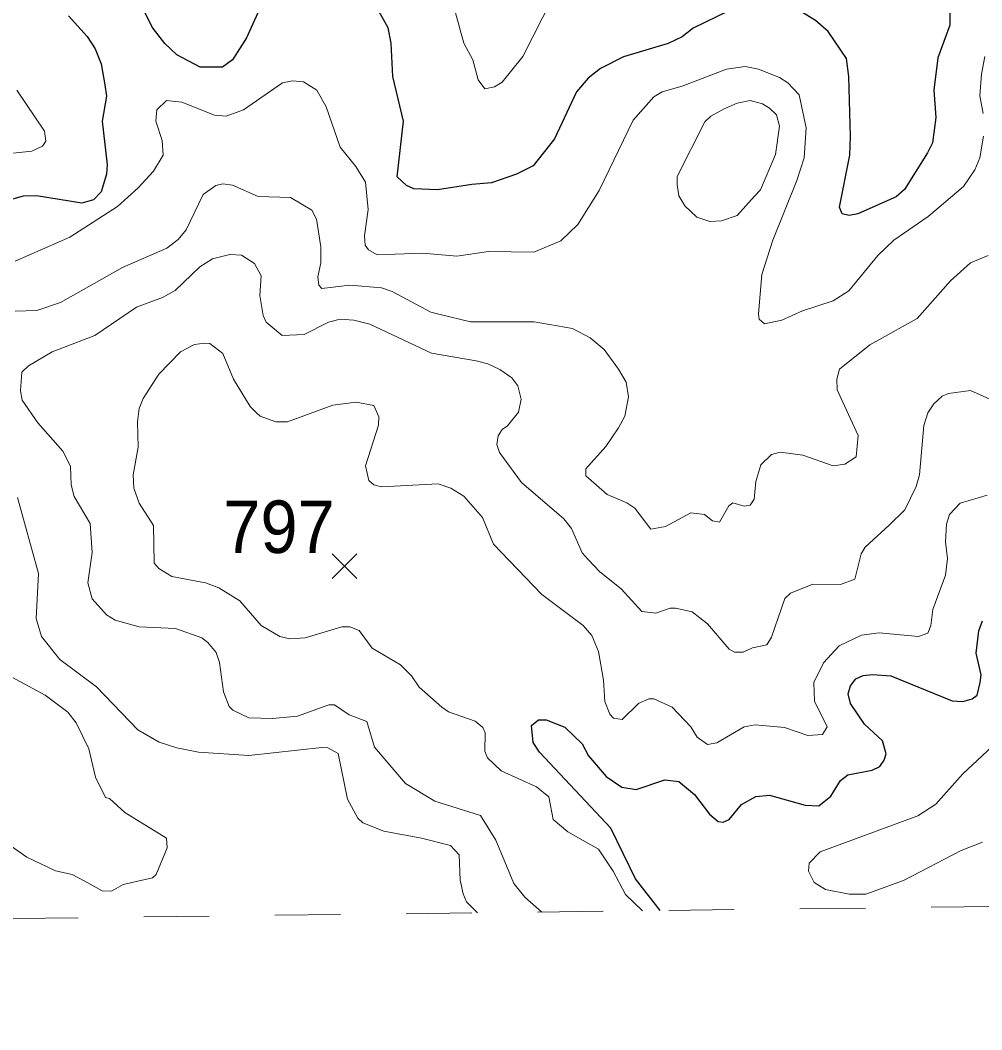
# Model space of a CAD drawing. Extents: x 294.2 to 320.3, y 7482.7 to 7510.7.
# Drawn here: x 307.613 to 309.078, y 7482.735 to 7484.274 of the extents above; entities that cross this region are included whole.
import ezdxf
from ezdxf.enums import TextEntityAlignment as Align

# ---------------------------------------------------------------- set-up
doc = ezdxf.new("R2010")
doc.units = 0
doc.header["$LTSCALE"] = 0.032
doc.linetypes.add('SHORT_DASHED', pattern=[2.7, 1.5, -1.2])
for name, color, linetype, lineweight in [('1', 7, 'Continuous', 25), ('2', 7, 'Continuous', 13), ('21', 7, 'Continuous', 25), ('22', 7, 'SHORT_DASHED', 13)]:
    doc.layers.add(name, color=color, linetype=linetype, lineweight=lineweight)
doc.layers.add('61', color=7, linetype='Continuous')

msp = doc.modelspace()

# ---------------------------------------------------------------- linework, layer by layer
at = {"layer": '1'}
for points in [[(307.9816, 7484.3005), (307.9572, 7484.2467), (307.9361, 7484.2134), (307.9211, 7484.2021), (307.8867, 7484.202), (307.8515, 7484.2207), (307.8328, 7484.2381), (307.8137, 7484.2631), (307.774, 7484.3434)], [(309.0219, 7484.3467), (309.0298, 7484.3166), (309.0292, 7484.2662), (309.0108, 7484.2163), (309.0047, 7484.1669), (309.0075, 7484.1255), (309.0025, 7484.0868)], [(307.6864, 7484.2801), (307.7147, 7484.2489), (307.7269, 7484.2301), (307.736, 7484.207), (307.7418, 7484.1752), (307.7441, 7484.158), (307.7377, 7484.12), (307.7449, 7484.0533), (307.7443, 7484.0393), (307.736, 7484.0124), (307.7244, 7484.0001), (307.7066, 7483.9947), (307.6373, 7484.006), (307.6173, 7484.0054), (307.3921, 7483.9415)], [(308.6922, 7484.2882), (308.6379, 7484.2614), (308.6212, 7484.2484), (308.6001, 7484.2382), (308.5319, 7484.2178), (308.4969, 7484.2), (308.478, 7484.1854), (308.4603, 7484.1645), (308.4269, 7484.0928), (308.3942, 7484.0519), (308.3687, 7484.039), (308.3309, 7484.0261), (308.3009, 7484.0234), (308.2482, 7484.0154), (308.2122, 7484.0165), (308.2011, 7484.0218), (308.1872, 7484.0352), (308.1967, 7484.1197), (308.1806, 7484.188), (308.1778, 7484.2385), (308.1734, 7484.2622), (308.159, 7484.2874)], [(309.0025, 7484.0868), (308.9953, 7484.0717), (308.9599, 7484.0158), (308.9471, 7484.0045), (308.8888, 7483.9787), (308.8755, 7483.976), (308.8649, 7483.9787), (308.8611, 7483.9889), (308.8765, 7484.068), (308.8776, 7484.0965), (308.8754, 7484.1877), (308.8716, 7484.2151), (308.8435, 7484.2566), (308.8243, 7484.2732), (308.8021, 7484.2867)], [(308.5878, 7482.917), (308.5499, 7482.9655), (308.5128, 7483.0424), (308.404, 7483.1586), (308.394, 7483.1731), (308.3918, 7483.1989), (308.4024, 7483.2075), (308.414, 7483.2075), (308.4423, 7483.1962), (308.469, 7483.1709), (308.4784, 7483.1526), (308.5056, 7483.1214), (308.5294, 7483.1052), (308.5513, 7483.1015), (308.5946, 7483.116), (308.6163, 7483.1139), (308.6401, 7483.094), (308.6628, 7483.0639), (308.6762, 7483.0526), (308.6839, 7483.0515), (308.6928, 7483.0558), (308.7116, 7483.0784), (308.7333, 7483.0908), (308.7544, 7483.093), (308.8088, 7483.0778), (308.8293, 7483.0768), (308.8476, 7483.0913), (308.8626, 7483.1154), (308.8737, 7483.124), (308.9109, 7483.131), (308.9225, 7483.1364), (308.9292, 7483.1461), (308.9319, 7483.1558), (308.9264, 7483.1757), (308.8992, 7483.2009), (308.8776, 7483.2327), (308.8743, 7483.2472), (308.8776, 7483.2596), (308.8859, 7483.2703), (308.897, 7483.2752), (308.9114, 7483.2768), (308.9391, 7483.2747), (309.0328, 7483.2365), (309.0489, 7483.2354), (309.0633, 7483.2397), (309.0705, 7483.2451), (309.0755, 7483.2645), (309.0766, 7483.2763), (309.0694, 7483.3091), (309.0733, 7483.343), (309.0788, 7483.3586)]]:
    msp.add_lwpolyline(points, dxfattribs=at)
at = {"layer": '2'}
for points in [[(308.424, 7484.309), (308.3787, 7484.2183), (308.3468, 7484.1794), (308.3353, 7484.1723), (308.3206, 7484.1691), (308.3104, 7484.1826), (308.3021, 7484.2132), (308.2887, 7484.2387), (308.2759, 7484.2847)], [(309.0823, 7484.2183), (309.0772, 7484.1915), (309.0746, 7484.1583), (309.0797, 7484.1315)], [(308.7426, 7483.8863), (308.7592, 7483.9387), (308.7962, 7484.0293), (308.8071, 7484.0638), (308.8103, 7484.1098), (308.7995, 7484.1602), (308.7822, 7484.178), (308.7694, 7484.1863), (308.7375, 7484.1991), (308.7171, 7484.2029), (308.689, 7484.1991), (308.6213, 7484.173), (308.5907, 7484.1646), (308.5779, 7484.157), (308.5466, 7484.1212), (308.4949, 7484.014), (308.4623, 7483.9623), (308.4362, 7483.9373), (308.3953, 7483.9201), (308.3264, 7483.9214), (308.2778, 7483.9143), (308.2255, 7483.9189), (308.1565, 7483.9163), (308.1433, 7483.9239), (308.1382, 7483.9311), (308.137, 7483.945), (308.1428, 7483.9851), (308.1386, 7484.0268), (308.1239, 7484.051), (308.1003, 7484.0804), (308.0786, 7484.1417), (308.0646, 7484.1672), (308.0441, 7484.18), (308.0276, 7484.1812), (308.0122, 7484.1781), (307.9528, 7484.1372), (307.9267, 7484.1276), (307.9088, 7484.1289), (307.859, 7484.1487), (307.8353, 7484.1513), (307.8206, 7484.1372), (307.8194, 7484.12), (307.829, 7484.0906), (307.8303, 7484.0682), (307.8155, 7484.0434), (307.7926, 7484.0184), (307.7607, 7483.9897), (307.6885, 7483.9431), (307.6049, 7483.9067)], [(307.6074, 7484.1672), (307.6495, 7484.1047), (307.6515, 7484.0893), (307.6464, 7484.0817), (307.6304, 7484.074), (307.587, 7484.0695)], [(309.0804, 7484.097), (309.0746, 7484.0638), (309.067, 7484.0459), (309.0498, 7484.0204), (308.9961, 7483.9744), (308.9438, 7483.9386), (308.9195, 7483.915), (308.8754, 7483.8614), (308.8512, 7483.8461)], [(308.3959, 7483.8141), (308.2989, 7483.8141), (308.2523, 7483.825), (308.2382, 7483.8288), (308.1795, 7483.8601), (308.1629, 7483.8658), (308.1147, 7483.8697), (308.0721, 7483.865), (308.0674, 7483.8697), (308.0662, 7483.8826), (308.0709, 7483.9042), (308.0709, 7483.9284), (308.0639, 7483.9706), (308.0569, 7483.984), (308.0243, 7484.0037), (307.9752, 7484.005), (307.9362, 7484.0223), (307.9216, 7484.0242), (307.9107, 7484.0216), (307.8915, 7484.0082), (307.8653, 7483.954), (307.8532, 7483.9393), (307.836, 7483.9265), (307.7683, 7483.8971), (307.6738, 7483.8435), (307.6381, 7483.8313), (307.6049, 7483.8301)], [(308.4073, 7482.9148), (308.3813, 7482.9375), (308.3646, 7482.958), (308.3372, 7483.0244), (308.3142, 7483.062), (308.2446, 7483.0837), (308.1999, 7483.1105), (308.1527, 7483.1661), (308.1406, 7483.205), (308.1137, 7483.2153), (308.0914, 7483.2306), (308.0831, 7483.2306), (308.0352, 7483.2133), (307.9969, 7483.2095), (307.9611, 7483.2107), (307.9368, 7483.2223), (307.9311, 7483.228), (307.9222, 7483.2504), (307.9164, 7483.2951), (307.9113, 7483.3104), (307.8986, 7483.3257), (307.8896, 7483.3327), (307.8494, 7483.3468), (307.7939, 7483.3493), (307.7575, 7483.3595), (307.7441, 7483.3678), (307.7224, 7483.3921), (307.7159, 7483.4164), (307.7223, 7483.4624), (307.7192, 7483.507), (307.6949, 7483.5479), (307.6904, 7483.5658), (307.6891, 7483.5939), (307.6776, 7483.6168), (307.6393, 7483.6603), (307.6157, 7483.6947), (307.6132, 7483.7088), (307.6151, 7483.7375), (307.6253, 7483.7471), (307.6611, 7483.7682), (307.7262, 7483.793), (307.79, 7483.8365), (307.8296, 7483.8512), (307.8488, 7483.862), (307.8864, 7483.8978), (307.9056, 7483.9099), (307.9318, 7483.9169), (307.9497, 7483.9156), (307.9695, 7483.9029), (307.9797, 7483.8844), (307.9777, 7483.8544), (307.9828, 7483.8237), (307.9873, 7483.8135), (308.0116, 7483.793), (308.0454, 7483.795), (308.0825, 7483.8135), (308.1003, 7483.818), (308.1208, 7483.8167), (308.1456, 7483.8103), (308.2395, 7483.7662), (308.3072, 7483.7547), (308.3251, 7483.7503), (308.3436, 7483.7413), (308.3615, 7483.7286), (308.371, 7483.7165), (308.3761, 7483.696), (308.3717, 7483.6762), (308.3551, 7483.6558), (308.3468, 7483.6501), (308.341, 7483.6405), (308.3391, 7483.6271), (308.3429, 7483.6149), (308.3764, 7483.5693), (308.4409, 7483.5139), (308.4526, 7483.4993), (308.4689, 7483.4623), (308.4778, 7483.4517), (308.4957, 7483.4332), (308.5282, 7483.4074), (308.56, 7483.3729), (308.5811, 7483.3704), (308.6028, 7483.378), (308.6111, 7483.378), (308.6366, 7483.3723), (308.6596, 7483.3538), (308.6931, 7483.3153), (308.7011, 7483.3106), (308.7144, 7483.3106), (308.7286, 7483.3174), (308.7503, 7483.3218), (308.7573, 7483.3334), (308.7778, 7483.3927), (308.7861, 7483.4004), (308.8205, 7483.4145), (308.8627, 7483.4138)], [(309.0874, 7483.915), (309.0606, 7483.9041), (309.03, 7483.8767), (308.9795, 7483.8192), (308.9074, 7483.779), (308.8608, 7483.742), (308.8569, 7483.7267), (308.8575, 7483.7107), (308.8895, 7483.6411), (308.8863, 7483.6085), (308.869, 7483.5971), (308.8512, 7483.5945), (308.8052, 7483.6111), (308.7707, 7483.6155), (308.7573, 7483.6117), (308.7413, 7483.5964), (308.7337, 7483.5709), (308.7311, 7483.5441), (308.7248, 7483.5345), (308.7158, 7483.5332), (308.6986, 7483.5383), (308.6922, 7483.5338), (308.6781, 7483.509), (308.6673, 7483.5108), (308.6552, 7483.5204), (308.6347, 7483.523), (308.596, 7483.5021), (308.5734, 7483.4981), (308.5492, 7483.53), (308.5371, 7483.5383), (308.507, 7483.5511), (308.4744, 7483.5792), (308.4744, 7483.59), (308.5051, 7483.6239), (308.5243, 7483.6526), (308.5339, 7483.6705), (308.5396, 7483.6999)], [(308.8512, 7483.8461), (308.8046, 7483.8307), (308.7733, 7483.8167), (308.7465, 7483.8109), (308.7388, 7483.8179), (308.7375, 7483.8263), (308.7426, 7483.8863)], [(308.5396, 7483.6999), (308.5357, 7483.7222), (308.5243, 7483.742), (308.5026, 7483.772), (308.4809, 7483.7899), (308.454, 7483.8039), (308.3959, 7483.8141)], [(308.5607, 7482.9166), (308.5351, 7482.9414), (308.516, 7482.9771), (308.4936, 7483.0103), (308.447, 7483.0371), (308.4246, 7483.0556), (308.4183, 7483.0901), (308.3992, 7483.1054), (308.3453, 7483.1301), (308.3247, 7483.1497), (308.3206, 7483.1599), (308.3212, 7483.1878), (308.3174, 7483.1961), (308.3059, 7483.2057), (308.2651, 7483.2197), (308.2549, 7483.2267), (308.2203, 7483.2574), (308.2089, 7483.2746), (308.1923, 7483.2912), (308.1488, 7483.3167), (308.129, 7483.3436), (308.115, 7483.3493), (308.1029, 7483.3493), (308.0467, 7483.3327), (308.0237, 7483.3308), (308.0084, 7483.3346), (307.9797, 7483.3512), (307.9471, 7483.3889), (307.9152, 7483.4087), (307.8948, 7483.4163), (307.8437, 7483.4259), (307.8239, 7483.438), (307.8168, 7483.4464), (307.8155, 7483.5038), (307.7938, 7483.5377), (307.7856, 7483.5607), (307.7849, 7483.5811), (307.7926, 7483.6232), (307.7913, 7483.6616), (307.7938, 7483.682), (307.8002, 7483.6973), (307.8239, 7483.7343), (307.857, 7483.7682), (307.8782, 7483.7797), (307.8935, 7483.7815), (307.9018, 7483.7809), (307.9215, 7483.7656), (307.9375, 7483.7267), (307.9631, 7483.6851), (307.9726, 7483.6756), (307.9784, 7483.6705), (308.002, 7483.6615), (308.0199, 7483.6615), (308.0889, 7483.687), (308.1246, 7483.6916), (308.1514, 7483.6864), (308.159, 7483.6692), (308.1584, 7483.6564), (308.1386, 7483.5945), (308.1437, 7483.5721), (308.1514, 7483.5657), (308.1629, 7483.5626), (308.2497, 7483.567), (308.2689, 7483.5606), (308.2887, 7483.5485), (308.3168, 7483.516), (308.334, 7483.4751), (308.4074, 7483.3985), (308.4706, 7483.3512), (308.4834, 7483.3359), (308.4936, 7483.3117), (308.5013, 7483.2683), (308.5032, 7483.2357), (308.5108, 7483.2165), (308.5166, 7483.2101), (308.53, 7483.2082), (308.5549, 7483.2325), (308.5703, 7483.2395), (308.5779, 7483.2395), (308.606, 7483.2267), (308.6347, 7483.1967), (308.6443, 7483.1814), (308.6597, 7483.1699), (308.6743, 7483.1724), (308.7158, 7483.1967), (308.7324, 7483.1999), (308.7771, 7483.1961), (308.8128, 7483.1839), (308.8352, 7483.1852), (308.8422, 7483.1967), (308.8231, 7483.2363), (308.8218, 7483.2644), (308.8365, 7483.2944), (308.8607, 7483.3206), (308.8946, 7483.3366)], [(308.9776, 7483.5632), (308.9827, 7483.5811), (308.9895, 7483.6562), (308.9957, 7483.6752), (309.0046, 7483.6892), (309.0172, 7483.7006), (309.0273, 7483.705), (309.0606, 7483.7094), (309.09, 7483.696)], [(308.8627, 7483.4138), (308.8844, 7483.4221), (308.894, 7483.4604), (308.9003, 7483.4706), (308.9367, 7483.5044), (308.9604, 7483.5275), (308.9776, 7483.5632)], [(307.6087, 7483.5466), (307.6406, 7483.4304), (307.6368, 7483.3621), (307.6451, 7483.3347), (307.6732, 7483.2995), (307.7287, 7483.258), (307.7919, 7483.1922), (307.8245, 7483.1737), (307.8513, 7483.1648), (307.8845, 7483.1584), (307.9612, 7483.1533), (308.0723, 7483.1655), (308.0812, 7483.1648), (308.0971, 7483.1565), (308.1112, 7483.0869), (308.1271, 7483.0576), (308.1348, 7483.0505), (308.1667, 7483.0378), (308.2242, 7483.0275), (308.2682, 7483.016), (308.2816, 7483.002), (308.2829, 7482.9631), (308.2874, 7482.9426), (308.2925, 7482.9305), (308.3094, 7482.9136)], [(309.0223, 7483.4279), (309.0255, 7483.4534), (309.0223, 7483.479), (309.0242, 7483.5058), (309.0286, 7483.5204), (309.0446, 7483.5377), (309.0862, 7483.5498)], [(308.8946, 7483.3366), (308.9214, 7483.3404), (308.9814, 7483.3346), (308.9954, 7483.3397), (309, 7483.3513), (309.0031, 7483.3755), (309.0223, 7483.4279)], [(307.601, 7483.272), (307.6509, 7483.2452), (307.6853, 7483.2191), (307.6981, 7483.2031), (307.7172, 7483.1635), (307.7274, 7483.1201), (307.7428, 7483.0894), (307.7485, 7483.0875), (307.7721, 7483.0664), (307.8353, 7483.0275), (307.8366, 7483.0126), (307.8199, 7482.9719), (307.8142, 7482.9669), (307.7694, 7482.9569), (307.7517, 7482.9464), (307.7377, 7482.9471), (307.7102, 7482.9624), (307.6917, 7482.972), (307.6662, 7482.9777), (307.6228, 7482.9982), (307.5902, 7483.0211)], [(309.0791, 7483.0212), (309.0466, 7483.0084), (308.9585, 7482.963), (308.901, 7482.942), (308.8755, 7482.942), (308.8397, 7482.949), (308.8225, 7482.9598), (308.8135, 7482.9771), (308.8148, 7482.9892), (308.8314, 7483.0065), (308.9802, 7483.0614), (309.0076, 7483.0792), (309.0491, 7483.1252), (309.1008, 7483.1738)]]:
    msp.add_lwpolyline(points, dxfattribs=at)
msp.add_lwpolyline([(308.7317, 7484.0056), (308.705, 7483.9763), (308.6814, 7483.968), (308.6635, 7483.9667), (308.6437, 7483.9738), (308.6251, 7483.991), (308.6162, 7484.0063), (308.6136, 7484.0229), (308.6136, 7484.0357), (308.6558, 7484.1187), (308.6647, 7484.1276), (308.6852, 7484.1385), (308.7049, 7484.1474), (308.7248, 7484.1513), (308.7439, 7484.1462), (308.7541, 7484.1398), (308.765, 7484.1295), (308.7694, 7484.1123), (308.7637, 7484.0689), (308.7407, 7484.0153)], close=True, dxfattribs=at)
at = {"layer": '21'}
for p, q in [((308.0878, 7483.4605), (308.1253, 7483.423)), ((308.1253, 7483.4605), (308.0878, 7483.423))]:
    msp.add_line(p, q, dxfattribs=at)
at = {"layer": '22'}
msp.add_lwpolyline([(294.6234, 7482.7353), (307.2008, 7482.9), (320.3015, 7483.0604)], dxfattribs=at)

# ---------------------------------------------------------------- texts
at = {"layer": '61', "width": 0.95}
msp.add_text('797', height=0.08, dxfattribs=at).set_placement((308.007, 7483.4618), align=Align.CENTER)

doc.saveas('drawing.dxf')
